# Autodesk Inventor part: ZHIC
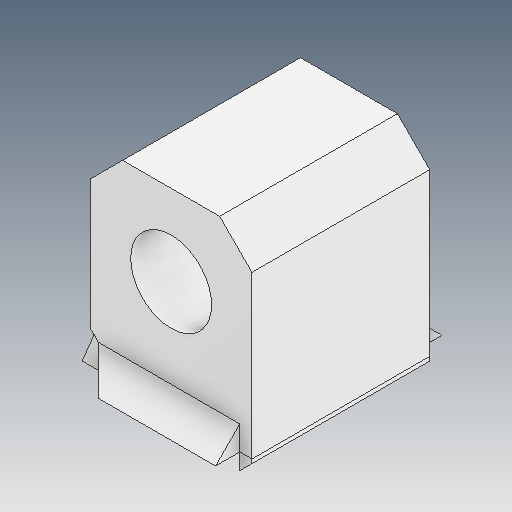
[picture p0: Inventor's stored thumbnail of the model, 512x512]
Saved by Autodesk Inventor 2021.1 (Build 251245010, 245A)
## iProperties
Created: 2021-05
Part Number: ZHIC
Material: Ogólny
Document SubType Name: Modeling
Designer: user
Density: 1 g/cm^3
Appearance: Domyślna
Author: user
Revision Number: ÈÎºÎ
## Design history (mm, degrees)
feature "ÊäÈë1"
feature "ÊäÈë2"
feature "ÊäÈë3"
feature "ÊäÈë4"
feature "ÊäÈë5"
node "Bryła1"
node "Bryła2"
node "Bryła3"
node "Bryła4"
node "Bryła5"
